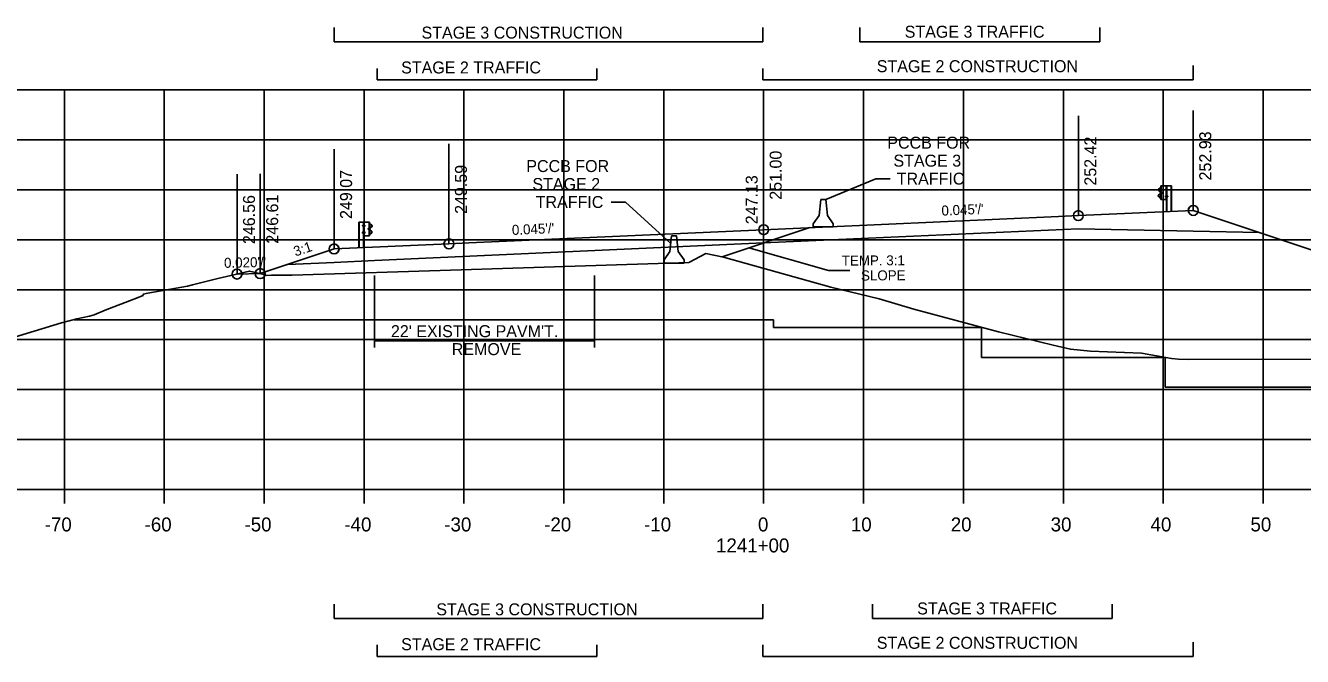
# Model space of a CAD drawing. Extents: x 1342547 to 1344156, y -1532351 to -1517216.
# Drawn here: x 1342629 to 1342756.8, y -1528822.1 to -1528758.9 of the extents above; entities that cross this region are included whole.
import ezdxf

# ---------------------------------------------------------------- set-up
doc = ezdxf.new("R2010")
doc.units = 0
for name, color, linetype in [('R_Alt Surface', 7, 'Continuous'), ('R_Axis', 7, 'Continuous'), ('R_Axis Annot', 7, 'Continuous'), ('R_Draft', 7, 'Continuous'), ('R_Exist Surface', 7, 'Continuous'), ('R_Fin Surface', 7, 'Continuous'), ('R_Grid', 7, 'Continuous'), ('R_MOT', 7, 'Continuous'), ('R_No Plot', 7, 'Continuous'), ('R_Xsect Elev', 7, 'Continuous'), ('R_Xsect Slope', 7, 'Continuous')]:
    doc.layers.add(name, color=color, linetype=linetype)

msp = doc.modelspace()

# ---------------------------------------------------------------- linework, layer by layer
at = {"layer": 'R_Alt Surface'}
for points in [[(1342745.87, -1528779.5), (1342734.37, -1528779.27), (1342702.87, -1528780.68)], [(1342745.87, -1528779.5), (1342752.51, -1528779.63)], [(1342663.92, -1528782.43), (1342702.87, -1528780.68)], [(1342655.24, -1528782.82), (1342659.87, -1528782.62)], [(1342659.87, -1528782.62), (1342663.92, -1528782.43)]]:
    msp.add_lwpolyline(points, dxfattribs=at)
at = {"layer": 'R_Axis'}
for p, q in [((1342562.87, -1528805.36), (1342842.87, -1528805.36)), ((1342632.87, -1528806.76), (1342632.87, -1528805.36)), ((1342642.87, -1528806.76), (1342642.87, -1528805.36)), ((1342652.87, -1528806.76), (1342652.87, -1528805.36)), ((1342662.87, -1528806.76), (1342662.87, -1528805.36)), ((1342672.87, -1528806.76), (1342672.87, -1528805.36)), ((1342682.87, -1528806.76), (1342682.87, -1528805.36)), ((1342692.87, -1528806.76), (1342692.87, -1528805.36)), ((1342702.87, -1528806.76), (1342702.87, -1528805.36)), ((1342712.87, -1528806.76), (1342712.87, -1528805.36)), ((1342722.87, -1528806.76), (1342722.87, -1528805.36)), ((1342732.87, -1528806.76), (1342732.87, -1528805.36)), ((1342742.87, -1528806.76), (1342742.87, -1528805.36)), ((1342752.87, -1528806.76), (1342752.87, -1528805.36))]:
    msp.add_line(p, q, dxfattribs=at)
at = {"layer": 'R_Draft'}
for p, q in [((1342659.87, -1528760.55), (1342659.87, -1528759.11)), ((1342702.78, -1528760.55), (1342702.78, -1528759.11)), ((1342712.51, -1528760.55), (1342712.51, -1528759.11)), ((1342736.51, -1528760.55), (1342736.51, -1528759.11)), ((1342659.87, -1528760.55), (1342702.78, -1528760.55)), ((1342712.51, -1528760.55), (1342736.51, -1528760.55)), ((1342664.18, -1528764.34), (1342664.18, -1528763.2)), ((1342686.18, -1528764.34), (1342686.18, -1528763.2)), ((1342702.78, -1528764.34), (1342702.78, -1528763.2)), ((1342745.87, -1528764.34), (1342745.87, -1528762.91)), ((1342664.18, -1528764.34), (1342686.18, -1528764.34)), ((1342702.78, -1528764.34), (1342745.87, -1528764.34)), ((1342742.66, -1528776.33), (1342742.66, -1528774.97)), ((1342743.16, -1528774.96), (1342743.17, -1528774.96)), ((1342743.16, -1528774.96), (1342743.23, -1528774.96)), ((1342743.19, -1528777.48), (1342743.19, -1528774.96)), ((1342743.66, -1528774.96), (1342743.66, -1528777.48)), ((1342743.69, -1528774.96), (1342743.69, -1528777.48)), ((1342742.39, -1528775.28), (1342742.52, -1528775.18)), ((1342742.56, -1528775.53), (1342742.39, -1528775.43)), ((1342742.51, -1528776.13), (1342742.39, -1528776.02)), ((1342742.4, -1528775.3), (1342742.53, -1528775.19)), ((1342742.58, -1528775.51), (1342742.4, -1528775.4)), ((1342742.53, -1528776.11), (1342742.4, -1528776)), ((1342742.41, -1528775.86), (1342742.57, -1528775.76)), ((1342742.43, -1528775.88), (1342742.58, -1528775.78)), ((1342742.63, -1528776.19), (1342742.51, -1528776.13)), ((1342742.52, -1528775.18), (1342742.63, -1528775.12)), ((1342742.53, -1528775.19), (1342742.62, -1528775.14)), ((1342742.63, -1528776.17), (1342742.53, -1528776.11)), ((1342742.6, -1528775.71), (1342742.6, -1528775.58)), ((1342742.62, -1528775.71), (1342742.62, -1528775.58)), ((1342742.67, -1528775.71), (1342742.67, -1528775.59)), ((1342742.67, -1528775.59), (1342742.72, -1528775.59)), ((1342742.67, -1528775.62), (1342742.72, -1528775.62)), ((1342742.67, -1528775.68), (1342742.72, -1528775.68)), ((1342742.67, -1528775.68), (1342742.72, -1528775.68)), ((1342742.67, -1528775.71), (1342742.72, -1528775.71)), ((1342742.73, -1528775.7), (1342742.73, -1528775.6)), ((1342743.15, -1528775.27), (1342743.1, -1528775.27)), ((1342743.1, -1528775.27), (1342743.1, -1528775.39)), ((1342743.15, -1528775.39), (1342743.1, -1528775.39)), ((1342743.1, -1528776.08), (1342743.1, -1528775.95)), ((1342743.1, -1528775.95), (1342743.15, -1528775.95)), ((1342743.1, -1528776.08), (1342743.15, -1528776.08)), ((1342743.11, -1528775.33), (1342743.16, -1528775.33)), ((1342743.11, -1528776.02), (1342743.16, -1528776.02)), ((1342743.16, -1528776.33), (1342743.2, -1528776.33)), ((1342743.23, -1528775.39), (1342743.23, -1528775.26)), ((1342743.23, -1528775.26), (1342743.28, -1528775.26)), ((1342743.23, -1528775.29), (1342743.28, -1528775.29)), ((1342743.23, -1528775.36), (1342743.27, -1528775.36)), ((1342743.23, -1528775.36), (1342743.28, -1528775.36)), ((1342743.23, -1528775.39), (1342743.28, -1528775.39)), ((1342743.24, -1528776.08), (1342743.24, -1528775.95)), ((1342743.24, -1528775.95), (1342743.29, -1528775.95)), ((1342743.24, -1528775.98), (1342743.29, -1528775.98)), ((1342743.24, -1528776.05), (1342743.28, -1528776.05)), ((1342743.24, -1528776.05), (1342743.29, -1528776.05)), ((1342743.24, -1528776.08), (1342743.29, -1528776.08)), ((1342743.29, -1528775.37), (1342743.29, -1528775.28)), ((1342743.3, -1528776.06), (1342743.3, -1528775.97)), ((1342662.35, -1528778.59), (1342662.35, -1528781.11)), ((1342662.38, -1528778.59), (1342662.38, -1528781.11)), ((1342662.75, -1528779), (1342662.75, -1528778.91)), ((1342662.81, -1528778.89), (1342662.76, -1528778.89)), ((1342662.81, -1528778.92), (1342662.76, -1528778.92)), ((1342662.88, -1528778.59), (1342662.81, -1528778.59)), ((1342662.81, -1528779.02), (1342662.81, -1528778.89)), ((1342662.84, -1528781.11), (1342662.84, -1528778.59)), ((1342662.88, -1528778.59), (1342662.87, -1528778.59)), ((1342662.88, -1528778.9), (1342662.93, -1528778.9)), ((1342662.93, -1528778.9), (1342662.93, -1528779.02)), ((1342663.37, -1528779.96), (1342663.37, -1528778.6)), ((1342663.52, -1528778.8), (1342663.41, -1528778.74)), ((1342663.51, -1528778.82), (1342663.41, -1528778.77)), ((1342663.64, -1528778.92), (1342663.51, -1528778.82)), ((1342663.65, -1528778.91), (1342663.52, -1528778.8)), ((1342662.74, -1528779.69), (1342662.74, -1528779.6)), ((1342662.8, -1528779.58), (1342662.75, -1528779.58)), ((1342662.8, -1528779.61), (1342662.75, -1528779.61)), ((1342662.8, -1528779.68), (1342662.75, -1528779.68)), ((1342662.8, -1528779.68), (1342662.75, -1528779.68)), ((1342662.8, -1528779.71), (1342662.75, -1528779.71)), ((1342662.81, -1528778.99), (1342662.76, -1528778.99)), ((1342662.81, -1528778.99), (1342662.76, -1528778.99)), ((1342662.81, -1528779.02), (1342662.76, -1528779.02)), ((1342662.8, -1528779.71), (1342662.8, -1528779.58)), ((1342662.87, -1528779.96), (1342662.84, -1528779.96)), ((1342662.93, -1528778.96), (1342662.87, -1528778.96)), ((1342662.93, -1528779.64), (1342662.87, -1528779.64)), ((1342662.88, -1528779.02), (1342662.93, -1528779.02)), ((1342662.93, -1528779.58), (1342662.88, -1528779.58)), ((1342662.93, -1528779.71), (1342662.88, -1528779.71)), ((1342662.93, -1528779.71), (1342662.93, -1528779.58)), ((1342663.36, -1528779.21), (1342663.31, -1528779.21)), ((1342663.31, -1528779.32), (1342663.31, -1528779.23)), ((1342663.36, -1528779.24), (1342663.31, -1528779.24)), ((1342663.36, -1528779.31), (1342663.31, -1528779.31)), ((1342663.36, -1528779.34), (1342663.31, -1528779.34)), ((1342663.36, -1528779.31), (1342663.32, -1528779.31)), ((1342663.36, -1528779.34), (1342663.36, -1528779.21)), ((1342663.4, -1528779.79), (1342663.51, -1528779.74)), ((1342663.41, -1528779.34), (1342663.42, -1528779.21)), ((1342663.41, -1528779.81), (1342663.52, -1528779.76)), ((1342663.44, -1528779.34), (1342663.44, -1528779.21)), ((1342663.46, -1528779.14), (1342663.63, -1528779.03)), ((1342663.61, -1528779.51), (1342663.46, -1528779.41)), ((1342663.47, -1528779.16), (1342663.65, -1528779.05)), ((1342663.62, -1528779.49), (1342663.47, -1528779.39)), ((1342663.51, -1528779.74), (1342663.64, -1528779.63)), ((1342663.52, -1528779.76), (1342663.65, -1528779.65)), ((1342663.92, -1528783.95), (1342663.92, -1528791.15)), ((1342685.92, -1528783.95), (1342685.92, -1528791.15)), ((1342663.92, -1528790.47), (1342685.92, -1528790.47)), ((1342659.86, -1528818.28), (1342659.86, -1528816.85)), ((1342702.78, -1528818.28), (1342702.78, -1528816.85)), ((1342713.75, -1528818.28), (1342713.75, -1528816.85)), ((1342737.75, -1528818.28), (1342737.75, -1528816.85)), ((1342659.86, -1528818.28), (1342702.78, -1528818.28)), ((1342713.75, -1528818.28), (1342737.75, -1528818.28)), ((1342664.18, -1528822.08), (1342664.18, -1528820.93)), ((1342686.18, -1528822.08), (1342686.18, -1528820.93)), ((1342702.78, -1528822.08), (1342702.78, -1528820.93)), ((1342745.87, -1528822.08), (1342745.87, -1528820.65)), ((1342664.18, -1528822.08), (1342686.18, -1528822.08)), ((1342702.78, -1528822.08), (1342745.87, -1528822.08))]:
    msp.add_line(p, q, dxfattribs=at)
for points in [[(1342714.09, -1528774.25), (1342709.08, -1528776.34)], [(1342715.53, -1528774.25), (1342714.09, -1528774.25)], [(1342743.69, -1528774.96), (1342743.23, -1528774.96), (1342743.23, -1528777.48)], [(1342687.59, -1528776.61), (1342689.04, -1528776.61)], [(1342689.04, -1528776.61), (1342693.57, -1528780.74)], [(1342662.35, -1528778.59), (1342662.81, -1528778.59), (1342662.8, -1528781.11)]]:
    msp.add_lwpolyline(points, dxfattribs=at)
for points in [[(1342742.64, -1528774.96), (1342742.64, -1528776.33), (1342743.16, -1528776.33), (1342743.16, -1528774.96)], [(1342742.68, -1528775.57), (1342742.68, -1528775.73), (1342742.67, -1528775.73), (1342742.67, -1528775.57)], [(1342742.73, -1528775.62), (1342742.73, -1528775.68), (1342742.76, -1528775.68), (1342742.76, -1528775.62)], [(1342743.11, -1528775.27), (1342743.11, -1528775.39), (1342743.16, -1528775.39), (1342743.16, -1528775.27)], [(1342743.11, -1528775.95), (1342743.11, -1528776.08), (1342743.16, -1528776.08), (1342743.16, -1528775.95)], [(1342743.23, -1528775.24), (1342743.23, -1528775.41), (1342743.22, -1528775.41), (1342743.22, -1528775.24)], [(1342743.24, -1528775.93), (1342743.24, -1528776.1), (1342743.23, -1528776.1), (1342743.23, -1528775.93)], [(1342743.29, -1528775.3), (1342743.29, -1528775.36), (1342743.31, -1528775.36), (1342743.31, -1528775.3)], [(1342743.3, -1528775.98), (1342743.3, -1528776.05), (1342743.32, -1528776.05), (1342743.32, -1528775.98)], [(1342662.75, -1528778.92), (1342662.75, -1528778.98), (1342662.72, -1528778.98), (1342662.72, -1528778.92)], [(1342662.8, -1528778.87), (1342662.8, -1528779.04), (1342662.81, -1528779.04), (1342662.81, -1528778.87)], [(1342663.4, -1528778.59), (1342663.4, -1528779.96), (1342662.87, -1528779.96), (1342662.88, -1528778.59)], [(1342662.93, -1528778.9), (1342662.93, -1528779.02), (1342662.88, -1528779.02), (1342662.88, -1528778.9)], [(1342662.74, -1528779.61), (1342662.74, -1528779.67), (1342662.71, -1528779.67), (1342662.71, -1528779.61)], [(1342662.79, -1528779.56), (1342662.79, -1528779.73), (1342662.8, -1528779.73), (1342662.8, -1528779.56)], [(1342662.93, -1528779.58), (1342662.93, -1528779.71), (1342662.88, -1528779.71), (1342662.88, -1528779.58)], [(1342663.3, -1528779.24), (1342663.3, -1528779.31), (1342663.28, -1528779.31), (1342663.28, -1528779.24)], [(1342663.36, -1528779.19), (1342663.36, -1528779.36), (1342663.37, -1528779.36), (1342663.37, -1528779.19)]]:
    msp.add_lwpolyline(points, close=True, dxfattribs=at)
for centre, radius, start, end in [((1342742.43, -1528775.35), 0.0856, 122.0217, 240.7501), ((1342742.47, -1528775.95), 0.109, 120.88, 214.7816), ((1342742.43, -1528775.35), 0.062, 122.0217, 240.7501), ((1342742.47, -1528775.95), 0.0854, 120.88, 214.7816), ((1342742.54, -1528775.59), 0.0622, 4.9556, 61.894), ((1342742.6, -1528775.65), 0.0453, 93.9303, 257.0446), ((1342742.55, -1528775.72), 0.0462, 293.1464, 8.2196), ((1342742.54, -1528775.59), 0.0865, 4.9556, 61.894), ((1342742.55, -1528775.72), 0.0703, 293.1464, 8.2196), ((1342742.71, -1528775.6), 0.022, 317.7756, 45.4255), ((1342742.64, -1528775.65), 0.0922, 339.7423, 20.2577), ((1342742.7, -1528775.7), 0.025, 323.3766, 39.0666), ((1342743.26, -1528775.28), 0.022, 317.7756, 45.4255), ((1342743.19, -1528775.33), 0.0922, 339.7423, 20.2577), ((1342743.26, -1528775.37), 0.025, 323.3766, 39.0666), ((1342743.27, -1528775.97), 0.022, 317.7756, 45.4255), ((1342743.2, -1528776.02), 0.0922, 339.7423, 20.2577), ((1342743.27, -1528776.06), 0.025, 323.3766, 39.0666), ((1342662.77, -1528778.91), 0.022, 134.5745, 222.2244), ((1342662.84, -1528778.95), 0.0922, 159.7423, 200.2577), ((1342663.6, -1528778.98), 0.062, 299.2499, 57.9783), ((1342663.6, -1528778.98), 0.0856, 299.2499, 57.9783), ((1342662.76, -1528779.6), 0.022, 134.5745, 222.2244), ((1342662.83, -1528779.64), 0.0922, 159.7423, 200.2577), ((1342662.77, -1528779.69), 0.025, 140.9334, 216.6234), ((1342662.78, -1528779), 0.025, 140.9334, 216.6234), ((1342663.33, -1528779.23), 0.022, 134.5745, 222.2244), ((1342663.4, -1528779.28), 0.0922, 159.7423, 200.2577), ((1342663.33, -1528779.32), 0.025, 140.9334, 216.6234), ((1342663.48, -1528779.35), 0.0703, 171.7804, 246.8536), ((1342663.5, -1528779.21), 0.0865, 118.106, 175.0444), ((1342663.5, -1528779.21), 0.0622, 118.106, 175.0444), ((1342663.43, -1528779.28), 0.0453, 282.9554, 86.0697), ((1342663.48, -1528779.35), 0.0462, 171.7804, 246.8536), ((1342663.57, -1528779.58), 0.0854, 325.2184, 59.12), ((1342663.57, -1528779.58), 0.109, 325.2184, 59.12)]:
    msp.add_arc(centre, radius, start, end, dxfattribs=at)
at = {"layer": 'R_Exist Surface'}
msp.add_lwpolyline([(1342624.33, -1528791.18), (1342632.58, -1528788.68), (1342634.1, -1528788.29), (1342635.37, -1528788), (1342635.84, -1528787.89), (1342636.96, -1528787.4), (1342639.82, -1528786.32), (1342640.75, -1528785.93), (1342640.75, -1528785.81), (1342641.23, -1528785.71), (1342645.21, -1528785), (1342645.68, -1528784.86), (1342646.37, -1528784.69), (1342648.23, -1528784.24), (1342651.41, -1528783.5), (1342652.85, -1528783.84), (1342653.07, -1528783.92), (1342653.61, -1528783.91), (1342655.67, -1528783.91), (1342672.58, -1528783.38), (1342695.4, -1528782.65), (1342695.42, -1528782.6), (1342695.46, -1528782.6), (1342697.07, -1528781.74), (1342698.85, -1528782.11), (1342707.32, -1528784.46), (1342709.58, -1528785.11), (1342714.44, -1528786.26), (1342717.89, -1528787.31), (1342726.37, -1528789.58), (1342731.84, -1528790.91), (1342733.58, -1528791.32), (1342735.58, -1528791.52), (1342740.68, -1528791.71), (1342743.7, -1528792.25), (1342744.39, -1528792.32), (1342745.42, -1528792.36), (1342759.83, -1528792.3)], dxfattribs=at)
at = {"layer": 'R_Fin Surface'}
for p, q in [((1342698.71, -1528782.07), (1342707.49, -1528779.14)), ((1342633.85, -1528788.36), (1342703.87, -1528788.36)), ((1342703.87, -1528789.13), (1342703.87, -1528788.36)), ((1342724.66, -1528792.13), (1342724.66, -1528789.13)), ((1342743.06, -1528795.11), (1342743.06, -1528792.13))]:
    msp.add_line(p, q, dxfattribs=at)
for points in [[(1342650.15, -1528783.79), (1342652.47, -1528783.75), (1342659.86, -1528781.28), (1342659.87, -1528781.28), (1342671.37, -1528780.77), (1342673.37, -1528780.68), (1342702.87, -1528779.35), (1342732.37, -1528778.03), (1342734.37, -1528777.94), (1342745.87, -1528777.42), (1342745.88, -1528777.42), (1342789.23, -1528791.87)], [(1342703.87, -1528789.13), (1342724.66, -1528789.13)], [(1342724.66, -1528792.13), (1342743.06, -1528792.13)], [(1342743.06, -1528795.11), (1342799.23, -1528795.11)]]:
    msp.add_lwpolyline(points, dxfattribs=at)
at = {"layer": 'R_Grid'}
for p, q in [((1342562.87, -1528765.36), (1342842.87, -1528765.36)), ((1342632.87, -1528805.36), (1342632.87, -1528765.36)), ((1342642.87, -1528805.36), (1342642.87, -1528765.36)), ((1342652.87, -1528805.36), (1342652.87, -1528765.36)), ((1342662.87, -1528805.36), (1342662.87, -1528765.36)), ((1342672.87, -1528805.36), (1342672.87, -1528765.36)), ((1342682.87, -1528805.36), (1342682.87, -1528765.36)), ((1342692.87, -1528805.36), (1342692.87, -1528765.36)), ((1342702.87, -1528805.36), (1342702.87, -1528765.36)), ((1342712.87, -1528805.36), (1342712.87, -1528765.36)), ((1342722.87, -1528805.36), (1342722.87, -1528765.36)), ((1342732.87, -1528805.36), (1342732.87, -1528765.36)), ((1342742.87, -1528805.36), (1342742.87, -1528765.36)), ((1342752.87, -1528805.36), (1342752.87, -1528765.36)), ((1342562.87, -1528770.36), (1342842.87, -1528770.36)), ((1342562.87, -1528775.36), (1342842.87, -1528775.36)), ((1342562.87, -1528780.36), (1342842.87, -1528780.36)), ((1342562.87, -1528785.36), (1342842.87, -1528785.36)), ((1342562.87, -1528790.36), (1342842.87, -1528790.36)), ((1342562.87, -1528795.36), (1342842.87, -1528795.36)), ((1342562.87, -1528800.36), (1342842.87, -1528800.36)), ((1342562.87, -1528805.36), (1342842.87, -1528805.36))]:
    msp.add_line(p, q, dxfattribs=at)
at = {"layer": 'R_MOT'}
for p, q in [((1342708.42, -1528777.92), (1342708.58, -1528776.34)), ((1342708.83, -1528776.34), (1342708.58, -1528776.34)), ((1342709.08, -1528776.34), (1342708.83, -1528776.34)), ((1342709.25, -1528777.92), (1342709.08, -1528776.34)), ((1342707.83, -1528779.08), (1342707.84, -1528778.75)), ((1342707.84, -1528778.75), (1342708.42, -1528777.92)), ((1342709.84, -1528778.75), (1342709.25, -1528777.92)), ((1342709.83, -1528779.08), (1342709.84, -1528778.75)), ((1342693.49, -1528781.53), (1342693.65, -1528779.95)), ((1342693.9, -1528779.95), (1342693.65, -1528779.95)), ((1342694.15, -1528779.95), (1342693.9, -1528779.95)), ((1342694.32, -1528781.53), (1342694.15, -1528779.95)), ((1342709.83, -1528779.08), (1342707.83, -1528779.08)), ((1342692.9, -1528782.7), (1342692.91, -1528782.37)), ((1342694.91, -1528782.7), (1342692.9, -1528782.7)), ((1342692.91, -1528782.37), (1342693.49, -1528781.53)), ((1342694.91, -1528782.37), (1342694.32, -1528781.53)), ((1342694.91, -1528782.7), (1342694.91, -1528782.37))]:
    msp.add_line(p, q, dxfattribs=at)
at = {"layer": 'R_No Plot'}
for centre in [(1342734.37, -1528777.94), (1342745.87, -1528777.42), (1342745.88, -1528777.42), (1342702.87, -1528779.35), (1342659.86, -1528781.28), (1342659.87, -1528781.28), (1342671.37, -1528780.77), (1342650.15, -1528783.79), (1342652.47, -1528783.75)]:
    msp.add_circle(centre, 0.5, dxfattribs=at)
at = {"layer": 'R_Xsect Elev'}
for p, q in [((1342745.87, -1528777.42), (1342745.87, -1528767.42)), ((1342745.88, -1528777.42), (1342745.88, -1528767.42)), ((1342734.37, -1528777.94), (1342734.37, -1528767.94)), ((1342702.87, -1528779.35), (1342702.87, -1528769.35)), ((1342671.37, -1528780.77), (1342671.37, -1528770.77)), ((1342659.86, -1528781.28), (1342659.86, -1528771.28)), ((1342659.87, -1528781.28), (1342659.87, -1528771.28)), ((1342650.15, -1528783.79), (1342650.15, -1528773.79)), ((1342652.47, -1528783.75), (1342652.47, -1528773.75)), ((1342702.87, -1528783.22), (1342702.87, -1528773.22)), ((1342701.38, -1528781.18), (1342709.37, -1528783.44)), ((1342709.37, -1528783.44), (1342711.51, -1528783.44))]:
    msp.add_line(p, q, dxfattribs=at)

# ---------------------------------------------------------------- texts
at = {"layer": 'R_Axis Annot'}
for s, p in [('-70', (1342630.9, -1528809.56)), ('-60', (1342640.9, -1528809.56)), ('-50', (1342650.9, -1528809.56)), ('-40', (1342660.9, -1528809.56)), ('-30', (1342670.9, -1528809.56)), ('-20', (1342680.9, -1528809.56)), ('-10', (1342690.9, -1528809.56)), ('0', (1342702.3, -1528809.56)), ('10', (1342711.6, -1528809.56)), ('20', (1342721.6, -1528809.56)), ('30', (1342731.6, -1528809.56)), ('40', (1342741.6, -1528809.56)), ('50', (1342751.6, -1528809.56)), ('1241+00', (1342698.1, -1528811.66))]:
    msp.add_text(s, height=1.4, dxfattribs=at).set_placement(p)
at = {"layer": 'R_Draft'}
for s, p in [('STAGE 3 CONSTRUCTION', (1342668.62, -1528760.22)), ('STAGE 3 TRAFFIC', (1342716.99, -1528760.13)), ('STAGE 2 TRAFFIC', (1342666.58, -1528763.71)), ('STAGE 2 CONSTRUCTION', (1342714.19, -1528763.58)), ('PCCB FOR', (1342715.25, -1528771.24)), ('PCCB FOR', (1342679.11, -1528773.58)), ('STAGE 3', (1342715.86, -1528773.04)), ('TRAFFIC', (1342716.19, -1528774.84)), ('STAGE 2', (1342679.72, -1528775.38)), ('TRAFFIC', (1342680.05, -1528777.18)), ("22' EXISTING PAVM'T.", (1342665.56, -1528790.11)), ('REMOVE', (1342671.65, -1528791.91)), ('STAGE 3 CONSTRUCTION', (1342670.1, -1528817.96)), ('STAGE 3 TRAFFIC', (1342718.24, -1528817.87)), ('STAGE 2 TRAFFIC', (1342666.58, -1528821.45)), ('STAGE 2 CONSTRUCTION', (1342714.19, -1528821.31))]:
    msp.add_text(s, height=1.2, dxfattribs=at).set_placement(p)
at = {"layer": 'R_Xsect Elev'}
for s, p in [('252.93', (1342747.67, -1528774.42)), ('252.93', (1342747.68, -1528774.42)), ('252.42', (1342736.17, -1528774.94)), ('251.00', (1342704.67, -1528776.35)), ('249.07', (1342661.66, -1528778.28)), ('249.07', (1342661.67, -1528778.28)), ('249.59', (1342673.17, -1528777.77)), ('247.13', (1342702.27, -1528778.81)), ('246.56', (1342651.95, -1528780.79)), ('246.61', (1342654.27, -1528780.75))]:
    msp.add_text(s, height=1.2, rotation=90, dxfattribs=at).set_placement(p)
at = {"layer": 'R_Xsect Slope'}
for s, rotation, p in [("0.045'/'", 2.5702, (1342720.69, -1528777.95)), ("0.045'/'", 2.5702, (1342677.69, -1528779.88)), ('3:1', 18.4349, (1342656, -1528782.04)), ("0.020'/'", 1.1458, (1342648.86, -1528783.17)), ('TEMP. 3:1', 0.3758, (1342710.69, -1528782.95)), ('SLOPE', 0.3758, (1342712.62, -1528784.44))]:
    msp.add_text(s, height=1, rotation=rotation, dxfattribs=at).set_placement(p)

doc.saveas('drawing.dxf')
